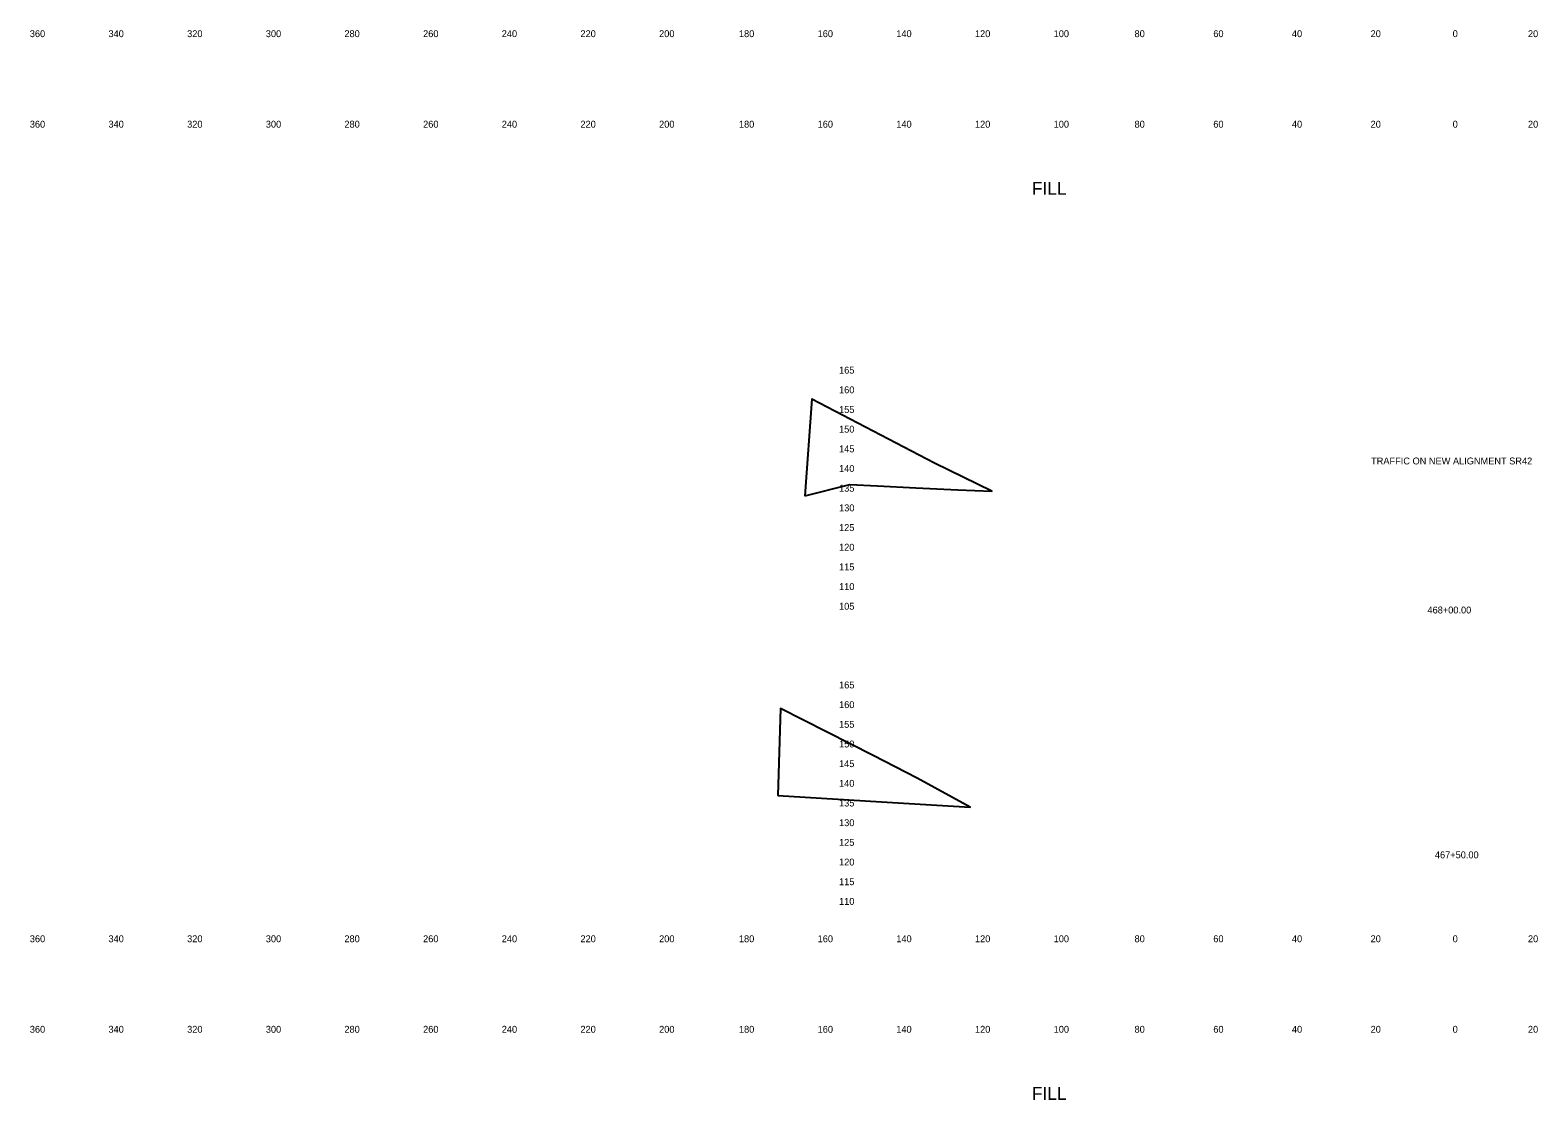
# Model space of a CAD drawing. Extents: x 21281 to 22024, y 6472 to 15208.
# Drawn here: x 21280.5 to 21663.8, y 9195.3 to 9467.1 of the extents above; entities that cross this region are included whole.
import ezdxf

# ---------------------------------------------------------------- set-up
doc = ezdxf.new("R2010")
doc.units = 0
for name, color, linetype in [('XS_SHEET_LABELS_ELEVATION', 7, 'Continuous'), ('XS_SHEET_LABELS_OFFSET', 7, 'Continuous'), ('XS_SHEET_LABELS_STATION', 7, 'Continuous'), ('XS_X_EXCESS', 7, 'Continuous')]:
    doc.layers.add(name, color=color, linetype=linetype)

msp = doc.modelspace()

# ---------------------------------------------------------------- linework, layer by layer
at = {"layer": 'XS_X_EXCESS'}
for points in [[(21477.41, 9348.74), (21488.88, 9351.62), (21495.91, 9351.29), (21505.66, 9350.83), (21516.35, 9350.33), (21524.97, 9349.93), (21510.44, 9357.06), (21494.84, 9365.18), (21479.23, 9373.31)], [(21470.58, 9272.59), (21499.7, 9270.84), (21519.48, 9269.65), (21506.03, 9277.07), (21494.84, 9282.76), (21471.28, 9294.73)]]:
    msp.add_lwpolyline(points, close=True, dxfattribs=at)

# ---------------------------------------------------------------- texts
at = {"layer": 'XS_SHEET_LABELS_ELEVATION'}
for s, p in [('  165  ', (21484.84, 9379.84)), ('  160  ', (21484.84, 9374.84)), ('  155  ', (21484.84, 9369.84)), ('  150  ', (21484.84, 9364.84)), ('  145  ', (21484.84, 9359.84)), ('  140  ', (21484.84, 9354.84)), ('  135  ', (21484.84, 9349.84)), ('  130  ', (21484.84, 9344.84)), ('  125  ', (21484.84, 9339.84)), ('  120  ', (21484.84, 9334.84)), ('  115  ', (21484.84, 9329.84)), ('  110  ', (21484.84, 9324.84)), ('  105  ', (21484.84, 9319.84)), ('  165  ', (21484.84, 9299.84)), ('  160  ', (21484.84, 9294.84)), ('  155  ', (21484.84, 9289.84)), ('  150  ', (21484.84, 9284.84)), ('  145  ', (21484.84, 9279.84)), ('  140  ', (21484.84, 9274.84)), ('  135  ', (21484.84, 9269.84)), ('  130  ', (21484.84, 9264.84)), ('  125  ', (21484.84, 9259.84)), ('  120  ', (21484.84, 9254.84)), ('  115  ', (21484.84, 9249.84)), ('  110  ', (21484.84, 9244.84))]:
    msp.add_text(s, height=1.75, dxfattribs=at).set_placement(p)
at = {"layer": 'XS_SHEET_LABELS_OFFSET'}
for s, height, p in [('  360  ', 1.75, (21279.14, 9465.34)), ('  340  ', 1.75, (21299.13, 9465.34)), ('  320  ', 1.75, (21319.13, 9465.34)), ('  300  ', 1.75, (21339.13, 9465.34)), ('  280  ', 1.75, (21359.1, 9465.34)), ('  260  ', 1.75, (21379.11, 9465.34)), ('  240  ', 1.75, (21399.1, 9465.34)), ('  220  ', 1.75, (21419.1, 9465.34)), ('  200  ', 1.75, (21439.1, 9465.34)), ('  180  ', 1.75, (21459.39, 9465.34)), ('  160  ', 1.75, (21479.4, 9465.34)), ('  140  ', 1.75, (21499.39, 9465.34)), ('  120  ', 1.75, (21519.39, 9465.34)), ('  100  ', 1.75, (21539.39, 9465.34)), ('  80  ', 1.75, (21559.95, 9465.34)), ('  60  ', 1.75, (21579.97, 9465.34)), ('  40  ', 1.75, (21599.95, 9465.34)), ('  20  ', 1.75, (21619.95, 9465.34)), ('  0  ', 1.75, (21640.81, 9465.34)), ('  0  ', 1.75, (21640.81, 9465.34)), ('  20  ', 1.75, (21659.95, 9465.34)), ('  360  ', 1.75, (21279.14, 9442.34)), ('  340  ', 1.75, (21299.13, 9442.34)), ('  320  ', 1.75, (21319.13, 9442.34)), ('  300  ', 1.75, (21339.13, 9442.34)), ('  280  ', 1.75, (21359.1, 9442.34)), ('  260  ', 1.75, (21379.11, 9442.34)), ('  240  ', 1.75, (21399.1, 9442.34)), ('  220  ', 1.75, (21419.1, 9442.34)), ('  200  ', 1.75, (21439.1, 9442.34)), ('  180  ', 1.75, (21459.39, 9442.34)), ('  160  ', 1.75, (21479.4, 9442.34)), ('  140  ', 1.75, (21499.39, 9442.34)), ('  120  ', 1.75, (21519.39, 9442.34)), ('  100  ', 1.75, (21539.39, 9442.34)), ('  80  ', 1.75, (21559.95, 9442.34)), ('  60  ', 1.75, (21579.97, 9442.34)), ('  40  ', 1.75, (21599.95, 9442.34)), ('  20  ', 1.75, (21619.95, 9442.34)), ('  0  ', 1.75, (21640.81, 9442.34)), ('  0  ', 1.75, (21640.81, 9442.34)), ('  20  ', 1.75, (21659.95, 9442.34)), ('FILL', 3.273, (21535.18, 9425.29)), ('  360  ', 1.75, (21279.14, 9235.34)), ('  340  ', 1.75, (21299.13, 9235.34)), ('  320  ', 1.75, (21319.13, 9235.34)), ('  300  ', 1.75, (21339.13, 9235.34)), ('  280  ', 1.75, (21359.1, 9235.34)), ('  260  ', 1.75, (21379.11, 9235.34)), ('  240  ', 1.75, (21399.1, 9235.34)), ('  220  ', 1.75, (21419.1, 9235.34)), ('  200  ', 1.75, (21439.1, 9235.34)), ('  180  ', 1.75, (21459.39, 9235.34)), ('  160  ', 1.75, (21479.4, 9235.34)), ('  140  ', 1.75, (21499.39, 9235.34)), ('  120  ', 1.75, (21519.39, 9235.34)), ('  100  ', 1.75, (21539.39, 9235.34)), ('  80  ', 1.75, (21559.95, 9235.34)), ('  60  ', 1.75, (21579.97, 9235.34)), ('  40  ', 1.75, (21599.95, 9235.34)), ('  20  ', 1.75, (21619.95, 9235.34)), ('  0  ', 1.75, (21640.81, 9235.34)), ('  0  ', 1.75, (21640.81, 9235.34)), ('  20  ', 1.75, (21659.95, 9235.34)), ('  360  ', 1.75, (21279.14, 9212.34)), ('  340  ', 1.75, (21299.13, 9212.34)), ('  320  ', 1.75, (21319.13, 9212.34)), ('  300  ', 1.75, (21339.13, 9212.34)), ('  280  ', 1.75, (21359.1, 9212.34)), ('  260  ', 1.75, (21379.11, 9212.34)), ('  240  ', 1.75, (21399.1, 9212.34)), ('  220  ', 1.75, (21419.1, 9212.34)), ('  200  ', 1.75, (21439.1, 9212.34)), ('  180  ', 1.75, (21459.39, 9212.34)), ('  160  ', 1.75, (21479.4, 9212.34)), ('  140  ', 1.75, (21499.39, 9212.34)), ('  120  ', 1.75, (21519.39, 9212.34)), ('  100  ', 1.75, (21539.39, 9212.34)), ('  80  ', 1.75, (21559.95, 9212.34)), ('  60  ', 1.75, (21579.97, 9212.34)), ('  40  ', 1.75, (21599.95, 9212.34)), ('  20  ', 1.75, (21619.95, 9212.34)), ('  0  ', 1.75, (21640.81, 9212.34)), ('  0  ', 1.75, (21640.81, 9212.34)), ('  20  ', 1.75, (21659.95, 9212.34)), ('FILL', 3.273, (21535.18, 9195.29))]:
    msp.add_text(s, height=height, dxfattribs=at).set_placement(p)
at = {"layer": 'XS_SHEET_LABELS_STATION'}
for s, p in [('TRAFFIC ON NEW ALIGNMENT SR42', (21621.38, 9356.76)), ('  468+00.00  ', (21634.41, 9318.89)), ('  467+50.00  ', (21636.29, 9256.67))]:
    msp.add_text(s, height=1.75, dxfattribs=at).set_placement(p)

doc.saveas('drawing.dxf')
